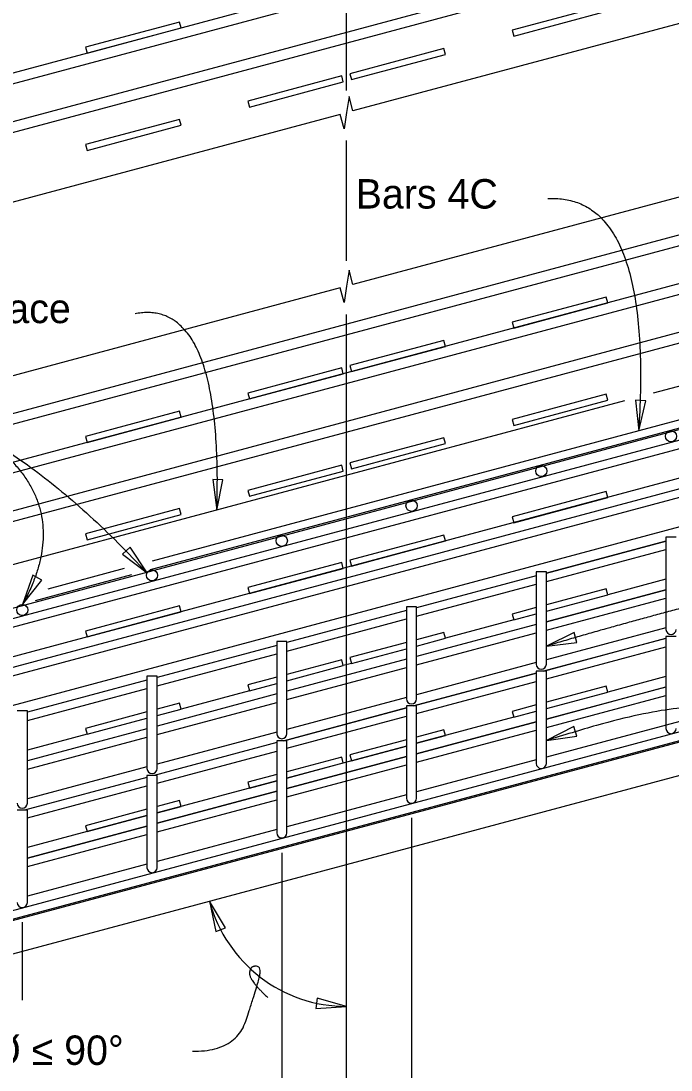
# Model space of a CAD drawing. Extents: x 120658.6 to 120712.1, y 120647.1 to 120669.9.
# Drawn here: x 120681 to 120684.34, y 120653.49 to 120658.88 of the extents above; entities that cross this region are included whole.
import ezdxf

# ---------------------------------------------------------------- set-up
doc = ezdxf.new("R2010")
doc.units = 0
for name, color, linetype in [('BeamConc', 7, 'Continuous'), ('CL_Major', 7, 'Continuous'), ('Dimension', 7, 'Continuous'), ('Rebar', 7, 'Continuous'), ('Rebar_h', 7, 'Continuous'), ('TextStructures', 7, 'Continuous')]:
    doc.layers.add(name, color=color, linetype=linetype)

msp = doc.modelspace()

# ---------------------------------------------------------------- linework, layer by layer
at = {"layer": 'BeamConc'}
for p, q in [((120685.5075, 120657.3022), (120684.2487, 120656.9649)), ((120684.1025, 120656.9257), (120679.8408, 120655.7838)), ((120687.0305, 120655.7103), (120679.2355, 120653.6216))]:
    msp.add_line(p, q, dxfattribs=at)
at = {"layer": 'CL_Major'}
for p, q in [((120682.6742, 120658.5204), (120682.6742, 120660.2234)), ((120682.6742, 120657.6448), (120682.6742, 120658.2638)), ((120682.6742, 120652.4249), (120682.6742, 120657.369))]:
    msp.add_line(p, q, dxfattribs=at)
at = {"layer": 'Dimension'}
for p, q in [((120683.0075, 120654.7827), (120683.0075, 120652.6851)), ((120682.3408, 120654.6042), (120682.3408, 120652.6851)), ((120681.0075, 120654.2468), (120681.0075, 120653.8457))]:
    msp.add_line(p, q, dxfattribs=at)
for points in [[(120684.7814, 120658.9716), (120682.7067, 120658.4158), (120682.6867, 120658.4906), (120682.6742, 120658.4071), (120682.6615, 120658.3234), (120682.6415, 120658.3983), (120680.6202, 120657.8569)], [(120685.0801, 120658.1592), (120682.7067, 120657.5235), (120682.6867, 120657.5983), (120682.6742, 120657.5147), (120682.6615, 120657.4311), (120682.6415, 120657.506), (120680.6202, 120656.9646)]]:
    msp.add_lwpolyline(points, dxfattribs=at)
for points in [[(120684.1753, 120656.7727), (120684.2112, 120656.9269), (120684.1584, 120656.9302)], [(120682.0078, 120656.3645), (120682.0388, 120656.5198), (120681.9859, 120656.5214)], [(120681.6484, 120656.0418), (120681.5615, 120656.1742), (120681.5227, 120656.1382)], [(120681.0094, 120655.8801), (120681.1076, 120656.0044), (120681.0611, 120656.0298)], [(120683.7002, 120655.6658), (120683.8575, 120655.685), (120683.8424, 120655.7358)], [(120683.7002, 120655.1801), (120683.857, 120655.2026), (120683.8408, 120655.253)], [(120681.9701, 120654.3543), (120682.0014, 120654.1995), (120682.0511, 120654.2187)], [(120682.6742, 120653.8141), (120682.5222, 120653.8572), (120682.5165, 120653.8042)]]:
    msp.add_lwpolyline(points, close=True, dxfattribs=at)
msp.add_arc((120682.6742, 120654.543), 0.7289, 195, 270, dxfattribs=at)
for points in [[(120683.7084, 120657.9654), (120684.2498, 120657.9937), (120684.1753, 120656.7727)], [(120682.0078, 120656.3645), (120682.0395, 120657.4586), (120681.5869, 120657.3737)], [(120679.9122, 120656.9718), (120680.71, 120657.051), (120681.6484, 120656.0418)], [(120680.7352, 120656.7842), (120681.3153, 120656.4395), (120681.0094, 120655.88)], [(120684.674, 120654.958), (120684.9813, 120656.0099), (120684.1308, 120655.7941), (120683.7002, 120655.6659)], [(120684.8882, 120654.6422), (120684.5913, 120654.6422), (120684.722, 120655.1213), (120684.5544, 120655.4544), (120683.7002, 120655.1801)], [(120681.8817, 120653.584), (120682.1042, 120653.5816), (120682.2095, 120653.9007), (120682.2402, 120654.0208), (120682.1752, 120654.0208), (120682.1752, 120653.9457), (120682.2693, 120653.8607)]]:
    msp.add_open_spline(points, degree=2, dxfattribs=at)
at = {"layer": 'Rebar'}
for p, q in [((120685.9982, 120657.2611), (120681.6743, 120656.1025)), ((120686.9134, 120657.1519), (120678.4242, 120654.8772)), ((120678.435, 120654.837), (120686.9242, 120657.1117)), ((120681.6668, 120656.0588), (120685.4194, 120657.0644)), ((120685.4351, 120657.0058), (120678.4242, 120655.1272)), ((120678.435, 120655.087), (120685.4459, 120656.9656)), ((120684.3148, 120656.2257), (120684.3148, 120655.7517)), ((120684.3669, 120656.2257), (120684.3148, 120656.2257)), ((120684.3148, 120656.2056), (120683.7002, 120656.041)), ((120683.7002, 120655.9978), (120684.3148, 120656.1625)), ((120681.5314, 120656.0642), (120681.138, 120655.9588)), ((120681.0752, 120655.9003), (120681.571, 120656.0332)), ((120683.6481, 120656.027), (120683.0335, 120655.8623)), ((120683.6481, 120656.0471), (120683.6481, 120655.5731)), ((120683.7002, 120656.0471), (120683.6481, 120656.0471)), ((120683.7002, 120655.5731), (120683.7002, 120656.0471)), ((120683.0335, 120655.8192), (120683.6481, 120655.9839)), ((120684.3148, 120655.9556), (120683.7002, 120655.791)), ((120683.7002, 120655.7478), (120684.3148, 120655.9125)), ((120682.9815, 120655.8484), (120682.3669, 120655.6837)), ((120682.9815, 120655.8684), (120682.9815, 120655.3944)), ((120683.0335, 120655.8684), (120682.9815, 120655.8684)), ((120683.0335, 120655.3944), (120683.0335, 120655.8684)), ((120682.3669, 120655.6406), (120682.9815, 120655.8052)), ((120683.6481, 120655.777), (120683.0335, 120655.6123)), ((120683.0335, 120655.5692), (120683.6481, 120655.7339)), ((120682.3148, 120655.6898), (120682.3148, 120655.2158)), ((120682.3669, 120655.6898), (120682.3148, 120655.6898)), ((120682.3669, 120655.2158), (120682.3669, 120655.6898)), ((120684.3148, 120655.7056), (120683.6857, 120655.5371)), ((120684.3148, 120655.7157), (120684.3148, 120655.2417)), ((120684.3669, 120655.7157), (120684.3148, 120655.7157)), ((120682.3148, 120655.6697), (120681.7002, 120655.5051)), ((120681.7002, 120655.4619), (120682.3148, 120655.6266)), ((120683.7002, 120655.4978), (120684.3148, 120655.6625)), ((120685.7448, 120655.5888), (120678.4242, 120653.6272)), ((120679.4781, 120653.8592), (120685.9781, 120655.6009)), ((120682.9815, 120655.5984), (120682.3669, 120655.4337)), ((120678.435, 120653.587), (120685.7573, 120655.549)), ((120682.3669, 120655.3906), (120682.9815, 120655.5552)), ((120683.6481, 120655.527), (120683.0188, 120655.3584)), ((120683.6481, 120655.5371), (120683.6481, 120655.0631)), ((120683.7002, 120655.5371), (120683.6481, 120655.5371)), ((120683.7002, 120655.0631), (120683.7002, 120655.5371)), ((120681.6481, 120655.4911), (120681.0335, 120655.3264)), ((120681.6481, 120655.5112), (120681.6481, 120655.0372)), ((120681.7002, 120655.5112), (120681.6481, 120655.5112)), ((120681.7002, 120655.0372), (120681.7002, 120655.5112)), ((120683.0335, 120655.3192), (120683.6481, 120655.4839)), ((120681.0335, 120655.2833), (120681.6481, 120655.448)), ((120682.3148, 120655.4197), (120681.7002, 120655.2551)), ((120684.3148, 120655.4556), (120683.7002, 120655.291)), ((120683.7002, 120655.2478), (120684.3148, 120655.4125)), ((120681.7002, 120655.2119), (120682.3148, 120655.3766)), ((120682.9815, 120655.3584), (120682.9815, 120654.8844)), ((120683.0335, 120655.3584), (120682.9815, 120655.3584)), ((120683.0335, 120654.8844), (120683.0335, 120655.3584)), ((120681.0335, 120655.3325), (120680.9815, 120655.3325)), ((120681.0335, 120654.8585), (120681.0335, 120655.3325)), ((120682.9815, 120655.3484), (120682.3523, 120655.1798)), ((120682.3669, 120655.1406), (120682.9815, 120655.3052)), ((120683.6481, 120655.277), (120683.0335, 120655.1123)), ((120681.6481, 120655.2411), (120681.0335, 120655.0764)), ((120681.0335, 120655.0333), (120681.6481, 120655.198)), ((120683.0335, 120655.0692), (120683.6481, 120655.2339)), ((120682.3148, 120655.1697), (120681.6857, 120655.0012)), ((120682.3148, 120655.1798), (120682.3148, 120654.7058)), ((120682.3669, 120655.1798), (120682.3148, 120655.1798)), ((120682.3669, 120654.7058), (120682.3669, 120655.1798)), ((120681.7002, 120654.9619), (120682.3148, 120655.1266)), ((120682.9815, 120655.0984), (120682.3669, 120654.9337)), ((120682.3669, 120654.8906), (120682.9815, 120655.0552)), ((120681.6481, 120654.9911), (120681.0188, 120654.8225)), ((120681.6481, 120655.0012), (120681.6481, 120654.5272)), ((120681.7002, 120655.0012), (120681.6481, 120655.0012)), ((120681.7002, 120654.5272), (120681.7002, 120655.0012)), ((120681.0335, 120654.7833), (120681.6481, 120654.948)), ((120682.3148, 120654.9197), (120681.7002, 120654.7551)), ((120681.7002, 120654.7119), (120682.3148, 120654.8766)), ((120681.0335, 120654.8225), (120680.9815, 120654.8225)), ((120681.0335, 120654.3485), (120681.0335, 120654.8225)), ((120681.6481, 120654.7411), (120681.0335, 120654.5764)), ((120681.0335, 120654.5333), (120681.6481, 120654.698))]:
    msp.add_line(p, q, dxfattribs=at)
for points in [[(120683.5326, 120658.8), (120684.0156, 120658.9294), (120684.0075, 120658.9596), (120683.5245, 120658.8302)], [(120681.3408, 120658.7127), (120681.8238, 120658.8421), (120681.8157, 120658.8723), (120681.3327, 120658.7429)], [(120682.6993, 120658.5767), (120683.1823, 120658.7061), (120683.1742, 120658.7363), (120682.6912, 120658.6069)], [(120682.1742, 120658.436), (120682.6571, 120658.5654), (120682.649, 120658.5956), (120682.1661, 120658.4662)], [(120681.3408, 120658.2127), (120681.8238, 120658.3421), (120681.8157, 120658.3723), (120681.3327, 120658.2429)], [(120683.5326, 120657.3), (120684.0156, 120657.4294), (120684.0075, 120657.4596), (120683.5245, 120657.3302)], [(120682.6993, 120657.0767), (120683.1823, 120657.2061), (120683.1742, 120657.2363), (120682.6912, 120657.1069)], [(120682.1742, 120656.936), (120682.6571, 120657.0654), (120682.649, 120657.0956), (120682.1661, 120656.9662)], [(120683.5326, 120656.8), (120684.0156, 120656.9294), (120684.0075, 120656.9596), (120683.5245, 120656.8302)], [(120681.3408, 120656.7127), (120681.8238, 120656.8421), (120681.8157, 120656.8723), (120681.3327, 120656.7429)], [(120682.6993, 120656.5767), (120683.1823, 120656.7061), (120683.1742, 120656.7363), (120682.6912, 120656.6069)], [(120682.1742, 120656.436), (120682.6571, 120656.5654), (120682.649, 120656.5956), (120682.1661, 120656.4662)], [(120683.5326, 120656.3), (120684.0156, 120656.4294), (120684.0075, 120656.4596), (120683.5245, 120656.3302)], [(120681.3408, 120656.2127), (120681.8238, 120656.3421), (120681.8157, 120656.3723), (120681.3327, 120656.2429)], [(120682.6993, 120656.0767), (120683.1823, 120656.2061), (120683.1742, 120656.2363), (120682.6912, 120656.1069)], [(120682.1742, 120655.936), (120682.6571, 120656.0654), (120682.649, 120656.0956), (120682.1661, 120655.9662)], [(120681.3408, 120655.7127), (120681.8238, 120655.8421), (120681.8157, 120655.8723), (120681.3327, 120655.7429)]]:
    msp.add_lwpolyline(points, close=True, dxfattribs=at)
for points in [[(120683.7002, 120655.8449), (120684.0156, 120655.9294), (120684.0075, 120655.9596), (120683.7002, 120655.8772)], [(120683.6481, 120655.8633), (120683.5245, 120655.8302), (120683.5326, 120655.8), (120683.6481, 120655.8309)], [(120683.0335, 120655.6662), (120683.1823, 120655.7061), (120683.1742, 120655.7363), (120683.0335, 120655.6986)], [(120682.9815, 120655.6846), (120682.6912, 120655.6069), (120682.6993, 120655.5767), (120682.9815, 120655.6523)], [(120682.3669, 120655.4876), (120682.6571, 120655.5654), (120682.649, 120655.5956), (120682.3669, 120655.52)], [(120682.3148, 120655.506), (120682.1661, 120655.4662), (120682.1742, 120655.436), (120682.3148, 120655.4737)], [(120683.7002, 120655.3449), (120684.0156, 120655.4294), (120684.0075, 120655.4596), (120683.7002, 120655.3772)], [(120681.7002, 120655.309), (120681.8238, 120655.3421), (120681.8157, 120655.3723), (120681.7002, 120655.3413)], [(120683.6481, 120655.3633), (120683.5245, 120655.3302), (120683.5326, 120655.3), (120683.6481, 120655.3309)], [(120681.6481, 120655.3274), (120681.3327, 120655.2429), (120681.3408, 120655.2127), (120681.6481, 120655.295)], [(120683.0335, 120655.1662), (120683.1823, 120655.2061), (120683.1742, 120655.2363), (120683.0335, 120655.1986)], [(120682.9815, 120655.1846), (120682.6912, 120655.1069), (120682.6993, 120655.0767), (120682.9815, 120655.1523)], [(120682.3669, 120654.9876), (120682.6571, 120655.0654), (120682.649, 120655.0956), (120682.3669, 120655.02)], [(120682.3148, 120655.006), (120682.1661, 120654.9662), (120682.1742, 120654.936), (120682.3148, 120654.9737)], [(120681.7002, 120654.809), (120681.8238, 120654.8421), (120681.8157, 120654.8723), (120681.7002, 120654.8413)], [(120681.6481, 120654.8274), (120681.3327, 120654.7429), (120681.3408, 120654.7127), (120681.6481, 120654.795)]]:
    msp.add_lwpolyline(points, dxfattribs=at)
for centre in [(120684.3408, 120656.7442), (120683.6742, 120656.5655), (120683.0075, 120656.3867), (120682.3408, 120656.2068), (120681.6742, 120656.0292), (120681.0075, 120655.8514)]:
    msp.add_circle(centre, 0.0287, dxfattribs=at)
for centre in [(120684.3408, 120655.7517), (120683.6742, 120655.5731), (120683.0075, 120655.3944), (120682.3408, 120655.2158), (120684.3408, 120655.2417), (120681.6742, 120655.0372), (120683.6742, 120655.0631), (120683.0075, 120654.8844), (120681.0075, 120654.8585), (120682.3408, 120654.7058), (120681.6742, 120654.5272), (120681.0075, 120654.3485)]:
    msp.add_arc(centre, 0.026, 179.9998, 359.9995, dxfattribs=at)
at = {"layer": 'Rebar_h'}
for p, q in [((120685.1478, 120657.9828), (120679.411, 120656.4456)), ((120679.0228, 120656.2877), (120685.1613, 120657.9325)), ((120685.2103, 120657.7495), (120679.411, 120656.1956)), ((120679.0228, 120656.0377), (120685.2238, 120657.6993)), ((120685.2728, 120657.5163), (120679.411, 120655.9456)), ((120679.0228, 120655.7877), (120685.2863, 120657.466)), ((120685.4216, 120657.0561), (120678.4356, 120655.1842)), ((120686.086, 120655.7341), (120683.7002, 120655.0949))]:
    msp.add_line(p, q, dxfattribs=at)
for points in [[(120686.8895, 120660.1994), (120678.4356, 120657.9342), (120678.449, 120657.884), (120686.9029, 120660.1492)], [(120686.8895, 120659.9494), (120678.4356, 120657.6842), (120678.449, 120657.634), (120686.9029, 120659.8992)]]:
    msp.add_lwpolyline(points, close=True, dxfattribs=at)
for points in [[(120686.0908, 120656.9854), (120679.2575, 120655.1545)], [(120686.0804, 120656.7327), (120679.2575, 120654.9045)], [(120683.7002, 120656.041), (120684.3148, 120656.2057)], [(120684.3148, 120656.0096), (120684.0156, 120655.9294)], [(120683.7002, 120655.791), (120684.3148, 120655.9557)], [(120683.5326, 120655.8), (120683.1823, 120655.7061)], [(120684.3148, 120655.7596), (120683.7002, 120655.5949)], [(120683.6854, 120655.5371), (120684.3148, 120655.7057)], [(120682.6993, 120655.5767), (120682.6571, 120655.5654)], [(120683.6481, 120655.5809), (120683.0335, 120655.4162)], [(120683.0185, 120655.3584), (120683.6481, 120655.5271)], [(120684.3148, 120655.5096), (120684.0156, 120655.4294)], [(120682.1742, 120655.436), (120681.8238, 120655.3421)], [(120683.7002, 120655.291), (120684.3148, 120655.4557)], [(120682.9815, 120655.4023), (120682.3669, 120655.2376)], [(120682.3521, 120655.1798), (120682.9815, 120655.3484)], [(120683.5326, 120655.3), (120683.0335, 120655.1662)], [(120683.0335, 120655.1124), (120683.6481, 120655.2771)], [(120681.3408, 120655.2127), (120681.0335, 120655.1303)], [(120682.3148, 120655.2237), (120681.7002, 120655.059)], [(120682.9815, 120655.1523), (120682.3669, 120654.9876)], [(120682.3669, 120654.9338), (120682.9815, 120655.0984)], [(120681.6481, 120655.045), (120681.0335, 120654.8803)], [(120683.6481, 120655.0809), (120683.0335, 120654.9162)], [(120682.3148, 120654.9737), (120681.7002, 120654.809)], [(120681.7002, 120654.7551), (120682.3148, 120654.9198)], [(120682.9815, 120654.9023), (120682.3669, 120654.7376)], [(120681.6481, 120654.795), (120681.0335, 120654.6303)], [(120681.0335, 120654.5765), (120681.6481, 120654.7412)], [(120682.3148, 120654.7237), (120681.7002, 120654.559)], [(120681.6481, 120654.545), (120681.0335, 120654.3803)]]:
    msp.add_lwpolyline(points, dxfattribs=at)

# ---------------------------------------------------------------- texts
at = {"layer": 'TextStructures'}
for s, p in [('Bars 4C', (120682.7206, 120657.9143)), ('Void Face', (120680.3464, 120657.3254)), ('75° ≤ Ø ≤ 90°', (120680.3133, 120653.5136))]:
    msp.add_text(s, height=0.1512, dxfattribs=at).set_placement(p)

doc.saveas('drawing.dxf')
